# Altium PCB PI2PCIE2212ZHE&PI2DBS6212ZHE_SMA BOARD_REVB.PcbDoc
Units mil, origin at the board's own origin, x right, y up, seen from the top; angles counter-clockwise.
Board outline 7950 x 1251 mil, 4 copper layers (Top Layer, InternalPlane1, InternalPlane2, Bottom Layer); 95 components, 10 nets, 912 pads, 56 vias.
Unrouted connection lines stored in the file: 12.
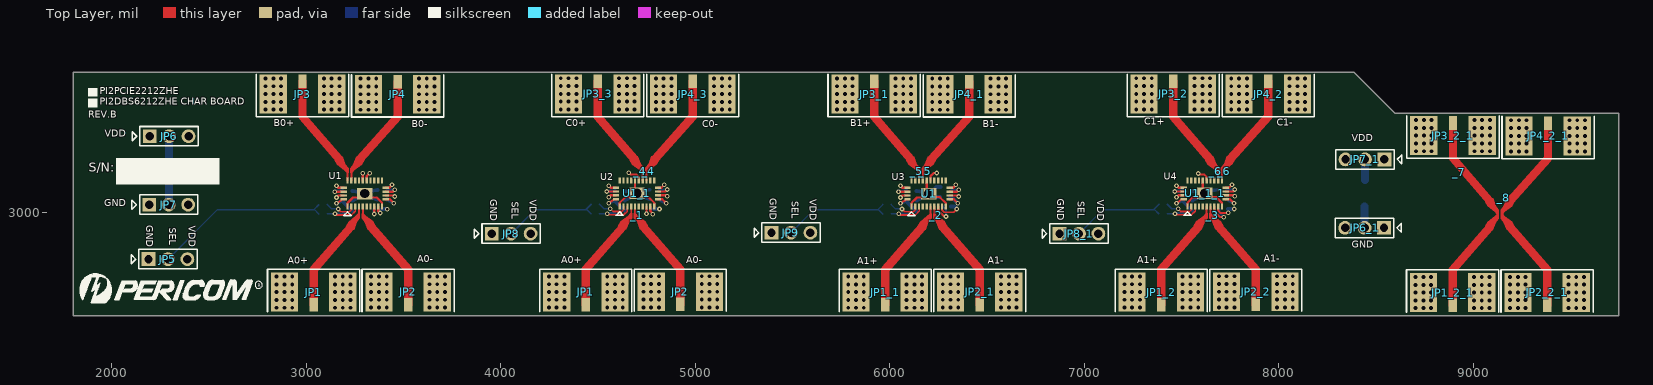
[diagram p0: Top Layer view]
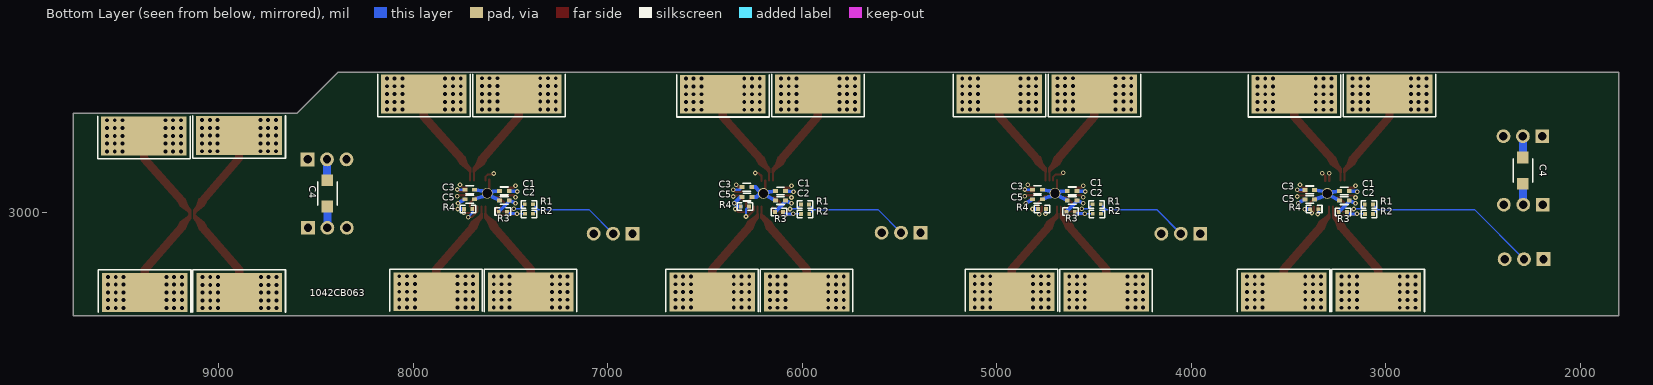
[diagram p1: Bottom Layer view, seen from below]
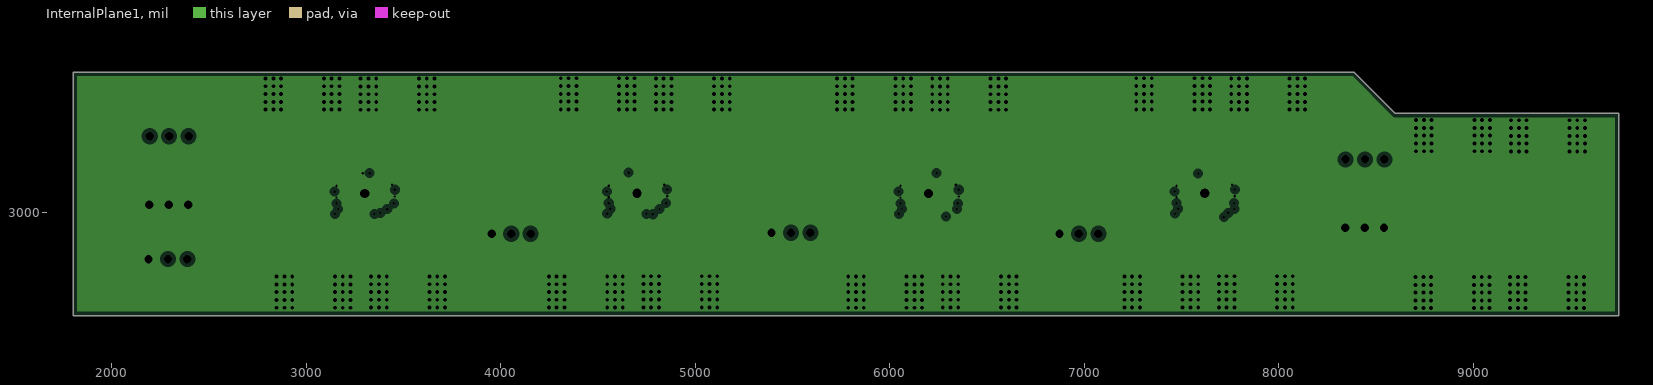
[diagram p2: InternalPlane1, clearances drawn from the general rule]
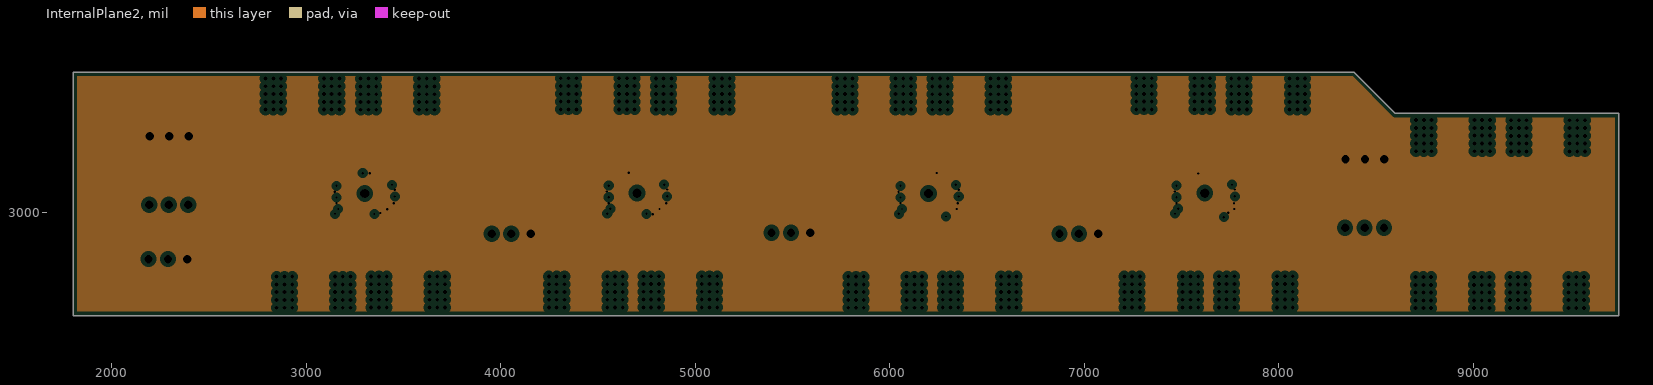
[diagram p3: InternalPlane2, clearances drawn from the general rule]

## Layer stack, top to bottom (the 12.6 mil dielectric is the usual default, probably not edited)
Top Layer: signal copper 1.4
Dielectric: core 12.6, FR-4, Dk 4.8
InternalPlane1: plane copper 1.4, net GND
Dielectric: prepreg 12.6, FR-4, Dk 4.8
InternalPlane2: plane copper 1.4, net VDD
Dielectric: core 12.6, FR-4, Dk 4.8
Bottom Layer: signal copper 1.4

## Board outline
1800,2472 9750,2472 9750,3511 8600,3511 8388,3723 1800,3723

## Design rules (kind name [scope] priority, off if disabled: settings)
Clearance [All] p1: gap=5
ComponentClearance [All] p1: gap=0 collisioncheckmode=3 verticalgap=0
HoleSize [All] p1: absolutevalues=TRUE maxlimit=500 minlimit=1 maxpercent=80.000 minpercent=20.000
PlaneClearance [All] p1: clearance=20
PlaneConnect [All] p1: planeconnectstyle=Direct reliefexpansion=20 reliefentries=4 reliefconductorwidth=10 reliefairgap=10
PolygonConnect [All] p1: connectstyle=Direct reliefconductorwidth=10 reliefentries=4 polygonreliefangle="90 Angle"
RoomDefinition "PI2DBS6212ZHE_CHAR BOAR" [InComponentClass('PI2DBS6212ZHE_CHAR BOAR')] p1: confinementstyle=ConfineIn formatcopy=TRUE lockcomponents=FALSE outline 35,220 10030,220 10030,6465 35,6465
RoutingVias [All] p1: holewidth=28 width=50 viastyle="Through Hole" minholewidth=8 minwidth=10 maxholewidth=28 maxwidth=50
SolderMaskExpansion [All] p1: expansion=4
TestPointUsage [All] p1: valid=0 allowmultiple=FALSE
Testpoint [All] p1: side=15 testpointundercomponent=TRUE minsize=40 maxsize=100 preferedsize=60 minholesize=0 maxholesize=40 preferedholesize=32 testpointgrid=1 style=1023 order=0123456789
Width [All] p1: maxlimit=150 minlimit=5 preferedwidth=10
15 further rules are at their usual default settings.

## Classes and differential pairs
component class "PI2DBS6212ZHE_CHAR BOAR": C1 C2 C3 C4 C5 JP1 JP2 JP3 JP4 JP5 JP6 JP7 R1 R2 R3 R4 U1

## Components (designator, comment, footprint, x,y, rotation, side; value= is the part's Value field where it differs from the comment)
_1 "" TRACE_650MIL_LD 4700.86,2988.73 r90 top
_2 "" TRACE_650MIL_LD 6240.23,2987.73 r90 top
_3 "" TRACE_650MIL_LD 7660.23,2988.71 r90 top
_4 "" TRACE_650MIL_LD 4718.11,3215.02 r270 top
_4 "" TRACE_650MIL_RD 4761.11,3215.02 r90 top
_5 "" TRACE_650MIL_LD 6139.37,3214.02 r270 top
_5 "" TRACE_650MIL_RD 6182.37,3214.02 r90 top
_6 "" TRACE_650MIL_LD 7677.48,3215 r270 top
_6 "" TRACE_650MIL_RD 7720.48,3215 r90 top
_7 "" TRACE_650MIL_LD 8929.1,3210.07 r270 top
_8 "" TRACE_650MIL_LD 9157.01,3078.64 r90 top
C1 "0.1u_0402" CC_0402 7532,3113 r0 bottom
C1 "0.1u_0402" CC_0402 6112,3112.02 r0 bottom
C1 "0.1u_0402" CC_0402 4612,3113.02 r0 bottom
C1 "0.1u_0402" CC_0402 3212,3112 r0 bottom
C2 "0.1u_0402" CC_0402 7532,3064 r0 bottom
C2 "0.1u_0402" CC_0402 6112,3063.02 r0 bottom
C2 "0.1u_0402" CC_0402 4612,3064.02 r0 bottom
C2 "0.1u_0402" CC_0402 3212,3063 r0 bottom
C3 "0.1u_0402" CC_0402 7710,3119 r180 bottom
C3 "0.1u_0402" CC_0402 6285,3132 r180 bottom
C3 "0.1u_0402" CC_0402 4790,3119.02 r180 bottom
C3 "0.1u_0402" CC_0402 3390,3118 r180 bottom
C4 "10u_1206" CC_1206 8442,3100 r90 bottom
C4 "10u_1206" CC_1206 2294,3217 r270 bottom
C5 "0.1u_0402" CC_0402 7710,3070 r180 bottom
C5 "0.1u_0402" CC_0402 6284,3081 r180 bottom
C5 "0.1u_0402" CC_0402 4790,3070.02 r180 bottom
C5 "0.1u_0402" CC_0402 3390,3069 r180 bottom
JP1 "RF_SMA_End" RF_SMA_End 4437,2693.02 r90 top
JP1 "RF_SMA_End" RF_SMA_End 3037,2692 r90 top
JP1_1 "RF_SMA_End" RF_SMA_End 5976.37,2692.02 r90 top (schematic designator JP1)
JP1_2 "RF_SMA_End" RF_SMA_End 7396.37,2693 r90 top (schematic designator JP1)
JP1_2_1 "RF_SMA_End" RF_SMA_End 8894.53,2689.93 r90 top (schematic designator JP1)
JP2 "RF_SMA_End" RF_SMA_End 4923,2694.02 r90 top
JP2 "RF_SMA_End" RF_SMA_End 3523,2693 r90 top
JP2_1 "RF_SMA_End" RF_SMA_End 6462.37,2693.02 r90 top (schematic designator JP2)
JP2_2 "RF_SMA_End" RF_SMA_End 7882.37,2694 r90 top (schematic designator JP2)
JP2_2_1 "RF_SMA_End" RF_SMA_End 9380.53,2690.93 r90 top (schematic designator JP2)
JP3 "RF_SMA_End" RF_SMA_End 2980,3511 r270 top
JP3_1 "RF_SMA_End" RF_SMA_End 5919.37,3511.02 r270 top (schematic designator JP3)
JP3_2 "RF_SMA_End" RF_SMA_End 7457.48,3512 r270 top (schematic designator JP3)
JP3_2_1 "RF_SMA_End" RF_SMA_End 8896.58,3297.07 r270 top (schematic designator JP3)
JP3_3 "RF_SMA_End" RF_SMA_End 4498.11,3512.02 r270 top (schematic designator JP3)
JP4 "RF_SMA_End" RF_SMA_End 3469,3510 r270 top
JP4_1 "RF_SMA_End" RF_SMA_End 6408.37,3510.02 r270 top (schematic designator JP4)
JP4_2 "RF_SMA_End" RF_SMA_End 7946.48,3511 r270 top (schematic designator JP4)
JP4_2_1 "RF_SMA_End" RF_SMA_End 9385.58,3296.07 r270 top (schematic designator JP4)
JP4_3 "RF_SMA_End" RF_SMA_End 4987.11,3511.02 r270 top (schematic designator JP4)
JP5 "3x1 Pin Header" "3x1 Pin Header" 2188,2762 r0 top
JP6 "3x1 Pin Header" "3x1 Pin Header" 2194,3394 r0 top
JP6_1 "3x1 Pin Header" "3x1 Pin Header" 8542,2923 r180 top (schematic designator JP6)
JP7 "3x1 Pin Header" "3x1 Pin Header" 2192,3042 r0 top
JP7_1 "3x1 Pin Header" "3x1 Pin Header" 8544,3275 r180 top (schematic designator JP7)
JP8 "3x1 Pin Header" "3x1 Pin Header" 3953,2893 r0 top (schematic designator JP5)
JP8_1 "3x1 Pin Header" "3x1 Pin Header" 6873,2892.98 r0 top (schematic designator JP5)
JP9 "3x1 Pin Header" "3x1 Pin Header" 5392,2898 r0 top (schematic designator JP5)
R1 "0" R_0402 3086,3043 r0 bottom
R1 "0" R_0402 5986,3043.02 r0 bottom
R1 "0" R_0402 7406,3044 r0 bottom
R1 "0" R_0402 4486,3044.02 r0 bottom
R2 "0" R_0402 3085,2994 r0 bottom
R2 "0" R_0402 5985,2994.02 r0 bottom
R2 "0" R_0402 7405,2995 r0 bottom
R2 "0" R_0402 4485,2995.02 r0 bottom
R3 "0" R_0402 3220,3005 r180 bottom
R3 "0" R_0402 6120,3005.02 r180 bottom
R3 "0" R_0402 7540,3006 r180 bottom
R3 "0" R_0402 4620,3006.02 r180 bottom
R4 "0" R_0402 3367,3019 r180 bottom
R4 "0" R_0402 4767,3020.02 r180 bottom
R4 "0" R_0402 6295,3033 r180 bottom
R4 "0" R_0402 7718,3020 r180 bottom
U1 "PI2DBS6212ZHE@TQFN28" TQFN28 6200,3099.02 r0 top
U1 "PI2DBS6212ZHE@TQFN28" TQFN28 3300,3099 r0 top
U1_1 "PI2DBS6212ZHE@TQFN28" TQFN28 4700,3100.02 r0 top (schematic designator U1)
U1_1_1 "PI2DBS6212ZHE@TQFN28" TQFN28 7620,3100 r0 top (schematic designator U1)
? "" "43 mil_Rogers" 7698.48,3222 r0 top
? "" "43 mil_Rogers" 6160.37,3221.02 r0 top
? "" "43 mil_Rogers" 4739.11,3222.02 r0 top
? "" "43 mil_Rogers" 7639.37,2983 r180 top
? "" "43 mil_Rogers" 6219.37,2982.02 r180 top
? "" "43 mil_Rogers" 4680,2983.02 r180 top
? "" TRACE_650MIL_LD 4674,3268 r270 top
? "" "43 mil_Rogers" 3221,3221 r0 top
? "" "43 mil_Rogers" 3280,2982 r180 top
? "" TRACE_650MIL_LD 7661.86,2988.72 r90 top
? "" TRACE_650MIL_LD 7493,3254 r270 top
? "" TRACE_650MIL_LD 3300.86,2987.72 r90 top
? "" TRACE_650MIL_RD 3257.86,2987.22 r270 top
? "" TRACE_650MIL_RD 3243,3214 r90 top
? "" TRACE_650MIL_LD 3200,3214 r270 top
? "" PSC_LOG 1940,2641 r0 top
? "" "43 mil_Rogers" 9137.58,3007.07 r0 top
? "" "43 mil_Rogers" 9137.53,2979.93 r180 top

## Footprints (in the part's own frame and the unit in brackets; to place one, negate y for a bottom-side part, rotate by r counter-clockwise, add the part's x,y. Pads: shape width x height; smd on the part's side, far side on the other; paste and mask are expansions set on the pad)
"3x1 Pin Header" [mm] "Pin Header 3x1 Pitch 2.54mm"
  rect 1.8x1.8 / inner round 1.8 / far side rect 1.8x1.8 hole 1.1: 1(0,0)
  round 1.8 hole 1.1: 2(2.54,0) 3(5.08,0)
  silkscreen extent -2.27,-1.27 6.35,1.27
"43 mil_Rogers" [mil]
  Top Layer region: 4.5,9.63 4.5,-13.85 14.94,-13.85 25.37,-1.93 62.99,26.75 75.28,47.48 74.23,68.36 35.23,68.36 20.51,30.23
  Top Layer region: -25.14,-2.29 -62.76,26.39 -75.05,47.12 -74,68 -35,68 -20.27,29.87 -4.5,9.57 -4.5,-14.21 -14.82,-14.21
CC_0402 [mil]
  rect 25x20 smd: 1(-25,0) 2(25,0)
  silkscreen extent -20,-20 20,20
CC_1206 [mil]
  rect 60x60 smd: 1(-67.5,0) 2(67.5,0)
  silkscreen extent -60,-50 60,50
PSC_LOG [mil]
  silkscreen extent -107,-103 833,45
R_0402 [mm]
  rect 0.5x0.5 smd: 1(-0.532,-0.001) 2(0.54,-0.001)
  silkscreen extent -1.02,-0.49 1.02,0.49
RF_SMA_End [mil] "PSF-S01B-2_FR4"
  rect 70x43 smd: 1(-165,0)
  rect 200x140 smd: 2(-100,-150) 3(-100,150)
  round 25 / inner round 35 / far side round 25 hole 20: 20(-180.02,190) 20(-180,-190) 20(-180,-150) 20(-180,-110) 20(-180,-110) 20(-180,110) 20(-180,150) 20(-140,-190) 20(-140,-150) 20(-140,110) 20(-140,150) 20(-140,190) 20(-140,-110) 20(-100,150) 20(-100,190) 20(-100,-110) 20(-100,110) 20(-100,-190) 20(-100,-150) 20(-60,190) 20(-60,110) 20(-60,150) 20(-60,-150) 20(-60,-110) 20(-60,-190) 20(-20,110) 20(-20,150) 20(-20,190) 20(-20,-110) 20(-20,-190) 20(-20,-150)
  rect 200x440 smd far side: 34(-100,0)
  silkscreen extent -201,-237 17,237
TQFN28 [mm] "TQFN28, 3.4x5.6mm, M10x4, Pitch 0.5mm"
  rect 0.3x0.8 smd: 1(-2.25,-1.7) 2(-1.75,-1.7) 3(-1.25,-1.7) 4(-0.75,-1.7) 5(-0.25,-1.7) 6(0.25,-1.7) 7(0.75,-1.7) 8(1.25,-1.7) 9(1.75,-1.7) 10(2.25,-1.7) 15(2.25,1.7) 16(1.75,1.7) 17(1.25,1.7) 18(0.75,1.7) 19(0.25,1.7) 20(-0.25,1.7) 21(-0.75,1.7) 22(-1.25,1.7) 23(-1.75,1.7) 24(-2.25,1.7)
  rect 0.8x0.3 smd: 11(2.75,-0.75) 12(2.75,-0.25) 13(2.75,0.25) 14(2.75,0.75) 25(-2.75,0.75) 26(-2.75,0.25) 27(-2.75,-0.25) 28(-2.75,-0.75)
  rect 2x1.5 smd: 29(0,0)
  round 1.4 hole 1.2: 29(0,0.025)
  silkscreen extent -2.74,-2.87 -1.78,-2.39
TRACE_650MIL_LD [mil]
TRACE_650MIL_RD [mil]

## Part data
C1 C1 C1 C1 C2 C2 C2 C2 C3 C3 C3 C3 C5 C5 C5 C5: library part C_0.1u_0402
C4 C4: library part C_10u_1206
R1 R1 R1 R1 R2 R2 R2 R2 R3 R3 R3 R3 R4 R4 R4 R4: library part "CHIP RES0402"

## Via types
v1: diameter 24, hole 12, Top Layer to Bottom Layer, tented both sides, 56 vias

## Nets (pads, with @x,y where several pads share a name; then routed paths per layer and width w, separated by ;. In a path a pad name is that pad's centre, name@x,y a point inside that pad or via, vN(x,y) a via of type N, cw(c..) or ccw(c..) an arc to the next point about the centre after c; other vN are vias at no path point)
A0+: JP1.1@3037,2527 U1.4@3270.47,3032.07 | length 516.6
  Top Layer w10: 3270.47,2986 U1.4@3270.47,3032.07
  Top Layer w43: JP1.1@3037,2527 3037,2709 3226.78,2926.32
A0-: JP2.1@3523,2528 U1.5@3290.16,3032.07 | length 517.2
  Top Layer w10: 3290.16,2985 U1.5@3290.16,3032.07
  Top Layer w43: 3333.15,2927.13 3523,2709 JP2.1@3523,2528
B0+: JP3.1 U1.24@3211.42,3165.93 | length 516.8
  Top Layer w10: U1.24@3211.42,3165.93 3211.42,3213.59
  Top Layer w43: JP3.1 2980,3494 3167.58,3276.64
B0-: JP4.1 U1.23@3231.1,3165.93 | length 520.8
  Top Layer w10: U1.23@3231.1,3165.93 3231.1,3213.29
  Top Layer w43: 3274.06,3275.95 3469,3494 JP4.1
GND: C1.2 C2.2 C3.2 C4.1@8442,3032.5 C4.2@2294,3149.5 C5.2 JP1.2 JP1.3 JP1.20 JP1.34 JP1_1.2 JP1_1.3 JP1_1.20 JP1_1.34 JP1_2.2 JP1_2.3 JP1_2.20 JP1_2.34 JP1_2_1.2 JP1_2_1.3 JP1_2_1.20 JP1_2_1.34 JP2.2 JP2.3 JP2.20 JP2.34 JP2_1.2 JP2_1.3 JP2_1.20 JP2_1.34 JP2_2.2 JP2_2.3 JP2_2.20 JP2_2.34 JP2_2_1.2 JP2_2_1.3 JP2_2_1.20 JP2_2_1.34 JP3.2 JP3.3 JP3.20 JP3.34 JP3_1.2 JP3_1.3 JP3_1.20 JP3_1.34 JP3_2.2 JP3_2.3 JP3_2.20 JP3_2.34 JP3_2_1.2 JP3_2_1.3 JP3_2_1.20 JP3_2_1.34 JP3_3.2 JP3_3.3 JP3_3.20 JP3_3.34 JP4.2 JP4.3 JP4.20 JP4.34 JP4_1.2 JP4_1.3 JP4_1.20 JP4_1.34 JP4_2.2 JP4_2.3 JP4_2.20 JP4_2.34 JP4_2_1.2 JP4_2_1.3 JP4_2_1.20 JP4_2_1.34 JP4_3.2 JP4_3.3 JP4_3.20 JP4_3.34 JP5.1 JP6_1.1 JP6_1.2 JP6_1.3 JP7.1 JP7.2 JP7.3 JP8.1 JP8_1.1 JP9.1 U1.1 U1.10 U1.12 U1.14 U1.20 U1.25 U1.27 U1.29 U1_1.1 U1_1.10 U1_1.12 U1_1.14 U1_1.20 U1_1.25 U1_1.27 U1_1.29 U1_1_1.1 U1_1_1.10 U1_1_1.12 U1_1_1.14 U1_1_1.20 U1_1_1.25 U1_1_1.27 U1_1_1.29 | length 2426.7
  Top Layer w11: U1.29@3328,3079 3361,3079 3388.58,3051.42 U1.10@3388.58,3032.07 ; U1_1.1 4611.42,3052.42 4640,3081 U1_1.29@4674,3081 ; U1_1.29@4732,3086 4754,3086 4788.58,3051.42 U1_1.10 ; U1.1@6111.42,3032.09 6111.42,3050.42 6140,3079 U1.29@6170,3079 ; U1.29@6230,3081 6258,3081 6288.58,3050.42 U1.10@6288.58,3032.09 ; U1_1_1.1 7531.42,3052.42 7559,3080 U1_1_1.29@7587,3080
  Top Layer w12: v1(3155,3079) 3165.16,3089.16 U1.27@3191.73,3089.16 ; v1(3155,3139) 3165.47,3128.53 U1.25@3191.73,3128.53 ; U1.1@3211.42,3032.07 3211.42,3051.42 3239,3079 U1.29@3266,3079 ; U1.20@3290.16,3165.93 v1@3290.16,3204 ; U1.12@3408.27,3089.16 3449.84,3089.16 v1(3455,3084) ; U1.14@3408.27,3128.53 3424.53,3128.53 v1(3440,3144) ; v1(4555,3080.02) 4565.16,3090.17 U1_1.27 ; v1(4555,3140.02) 4565.47,3129.54 U1_1.25 ; U1_1.29@4690.16,3123.84 U1_1.20 ; U1_1.12 4849.84,3090.17 v1(4855,3085.02) ; U1_1.14 4824.53,3129.54 v1(4840,3145.02) ; v1(6055,3079.02) 6065.16,3089.17 U1.27@6091.73,3089.17 ; v1(6055,3139.02) 6065.47,3128.54 U1.25@6091.73,3128.54 ; U1.29@6190,3112 U1.20@6190,3165.94 ; U1.12@6308.27,3089.17 6349.84,3089.17 v1(6355,3084.02) ; U1.14@6308.27,3128.54 6324.53,3128.54 v1(6340,3144.02) ; v1(7475,3080) 7485.16,3090.16 U1_1_1.27 ; v1(7475,3140) 7485.47,3129.53 U1_1_1.25 ; U1_1_1.29@7610,3127 U1_1_1.20@7610,3170.1 ; U1_1_1.29@7651,3080 7680,3080 7708.58,3051.42 U1_1_1.10 ; U1_1_1.12 7769.84,3090.16 v1(7775,3085) ; U1_1_1.14 7744.53,3129.53 v1(7760,3145)
  Bottom Layer w20: C2.2@3237,3063 3274,3083 ; C1.2@3237,3112 3271,3108 ; 3323,3084 C5.2@3365,3069 ; U1.29@3325,3111 C3.2@3365,3118 ; C2.2@4637,3064 4674,3084 ; C1.2@4637,3113 4671,3109 ; 4723,3085 C5.2@4765,3070 ; U1_1.29@4725,3112 C3.2@4765,3119 ; C2.2@6137,3063 6174,3083 ; C1.2@6137,3112 6171,3108 ; U1.29@6222,3113 6241,3132 C3.2@6260,3132 ; U1.29@6225,3092 6236,3081 C5.2@6259,3081 ; C2.2@7557,3064 7594,3084 ; C1.2@7557,3113 7591,3109 ; 7643,3085 C5.2@7685,3070 ; U1_1_1.29@7645,3112 C3.2@7685,3119
  Bottom Layer w40: JP7.2@2294,3044 C4.2@2294,3149.5 ; JP6_1.2@8442,2923.5 C4.1@8442,3033
  other v1: 3290,3204
NetR1_2: R1.2 U1.2 U1_1.2 U1_1_1.2 | length 639.6
  Top Layer w8: v1(3163,3020) 3177,3006 3222,3006 3231.1,3015.1 U1.2@3231.1,3032.07 ; v1(4563,3021.02) 4577,3007.02 4622,3007.02 4631.1,3016.12 U1_1.2 ; v1(6063,3020.02) 6077,3006.02 6122,3006.02 6131.1,3015.12 U1.2@6131.1,3032.09 ; v1(7483,3021) 7497,3007 7542,3007 7551.1,3016.1 U1_1_1.2
  Bottom Layer w8: R1.2@3107.27,3043.03 3130.3,3020 v1(3163,3020) ; R1.2@4506.97,3044.03 4530,3021 v1@4562.7,3021 ; R1.2@6006.97,3043.03 6030,3020 v1@6062.7,3020 ; R1.2@7427.27,3044.03 7450.3,3021 v1(7483,3021)
NetR2_2: R2.2@3106.27,2994.03 R3.2@3198.73,3004.97 U1.3@3250.79,3032.07 | length 234
  Top Layer w8: v1(3147,2995) 3153,2989 3232,2989 3250.79,3007.79 U1.3@3250.79,3032.07
  Bottom Layer w8: R2.2@3107.24,2995 v1(3147,2995)
  Bottom Layer w15: v1(3147,2995) 3188.76,2995 R3.2@3198.73,3004.97
NetR4_2: R4.2 U1.8 U1_1.8 U1_1_1.8 | length 393.2
  Top Layer w11: v1(3349.21,2993.79) U1.8@3349.21,3032.07 ; v1(4749.21,2994.8) U1_1.8 ; U1.8@6249.21,3032.09 6249.21,3011.79 6280,2981 v1(6289,2981) ; U1_1_1.8 7669.21,3007.79 7699,2978 v1(7718,2978)
  Bottom Layer w11: R4.2@3345.73,3018.97 3345.73,2997.27 v1(3349.21,2993.79) ; v1(4749.21,2994.8) R4.2@4749.21,3016.5 ; R4.2@6273.73,3032.97 6289,3017.7 v1(6289,2981) ; R4.2@7696.73,3019.97 7696.73,2999.27 v1(7718,2978)
SEL: JP5.2 JP8.2 JP8_1.2 JP9.2 R1.1 R2.1 R2.2@4506.27,2995.05 R2.2@6006.27,2994.05 R2.2@7426.27,2995.03 R3.2@4598.73,3005.98 R3.2@6098.73,3004.98 R3.2@7518.73,3005.97 U1.3@6150.79,3032.09 U1_1.3 U1_1_1.3 | length 3173.9
  Top Layer w8: v1(4547,2996.02) 4553,2990.02 4632,2990.02 4650.79,3008.8 U1_1.3 ; v1(6047,2995.02) 6053,2989.02 6132,2989.02 6150.79,3007.8 U1.3@6150.79,3032.09 ; v1(7467,2996) 7473,2990 7552,2990 7570.79,3008.79 U1_1_1.3
  Bottom Layer w8: JP5.2 2543,3017 3041.08,3017 R2.1@3064.05,2994.03 ; 3039,3017 R1.1@3064,3042 ; JP8.2 4176,3016 4443.1,3016 R2.1@4464.05,2995.05 ; 4437,3016 R1.1@4465.05,3044.05 ; R2.2@4507.24,2996.02 v1(4547,2996.02) ; JP9.2 5611,3017 5941.1,3017 R2.1@5964.05,2994.05 ; 5939,3017 R1.1@5965.05,3043.05 ; R2.2@6007.24,2995.02 v1(6047,2995.02) ; JP8_1.2 7097.02,3017 7362.08,3017 R2.1@7384.05,2995.03 ; 7358.02,3017 R1.1@7385.05,3044.03 ; R2.2@7427.24,2996 v1(7467,2996)
  Bottom Layer w15: v1(4547,2996.02) 4588.76,2996.02 ; v1(6047,2995.02) 6088.76,2995.02 ; v1(7467,2996) 7508.76,2996
VDD: C1.1 C2.1 C3.1 C4.1@2294,3284.5 C4.2@8442,3167.5 C5.1 JP5.3 JP6.1 JP6.2 JP6.3 JP7_1.1 JP7_1.2 JP7_1.3 JP8.3 JP8_1.3 JP9.3 R3.1 R4.1 U1.9 U1.11 U1.13 U1.19 U1.26 U1.28 U1_1.9 U1_1.11 U1_1.13 U1_1.19 U1_1.26 U1_1.28 U1_1_1.9 U1_1_1.11 U1_1_1.13 U1_1_1.19 U1_1_1.26 U1_1_1.28 | length 2583.6
  Top Layer w10: v1(4657,3207) 4667,3197 4698,3197 4709.84,3185.16 U1_1.19 ; U1.9@6268.9,3032.09 6268.9,3014.1 6280,3003 6328.06,3003 v1(6345.03,3019.97) ; v1(7586,3202) 7591.02,3196.98 7618,3196.98 7629.84,3185.14 U1_1_1.19 ; U1_1_1.9 7688.9,3011.1 7700,3000 v1(7741,3000)
  Top Layer w12: v1@3145,3108.84 U1.26@3191.73,3108.84 ; v1(3155,3049) 3185.47,3069.47 U1.28@3191.73,3069.47 ; U1.19@3309.84,3165.93 3309.84,3188.84 v1(3325,3204) ; U1.9@3368.9,3032.07 3368.9,3010.1 v1(3380,2999) ; U1.11@3408.27,3069.47 3429.53,3069.47 v1(3450,3049) ; U1.13@3408.27,3108.84 3444.84,3108.84 v1(3455,3119) ; v1(4545,3109.86) U1_1.26 ; v1(4555,3050.02) 4585.47,3070.49 U1_1.28 ; U1_1.9 4768.9,3011.12 v1(4782,2993) ; U1_1.11 4829.53,3070.49 v1(4850,3050.02) ; U1_1.13 4844.84,3109.86 v1(4855,3120.02) ; v1(6045,3108.86) U1.26@6091.73,3108.86 ; v1(6055,3049.02) 6085.47,3069.49 U1.28@6091.73,3069.49 ; U1.19@6209.84,3165.94 6209.84,3188.86 6225.98,3205 v1(6241,3205) ; U1.11@6308.27,3069.49 6329.53,3069.49 v1(6350,3049.02) ; U1.13@6308.27,3108.86 6344.84,3108.86 v1(6355,3119.02) ; v1(7465,3109.84) U1_1_1.26 ; v1(7475,3050) 7505.47,3070.47 U1_1_1.28 ; U1_1_1.11 7749.53,3070.47 v1(7770,3050) ; U1_1_1.13 7764.84,3109.84 v1(7775,3120)
  Bottom Layer w14: C3.1@6310,3132 6322.98,3119.02 v1(6355,3119.02)
  Bottom Layer w15: C3.1@3415,3118 v1(3455,3119) ; C3.1@4815,3119.02 v1(4855,3120.02) ; C3.1@7735,3119 v1(7775,3120)
  Bottom Layer w20: v1(3145,3109) C1.1@3187,3112 ; v1(3155,3049) 3185.5,3062.34 C2.1@3187,3063 ; C2.1@3187,3058.92 R3.1@3240.95,3004.97 ; R4.1@3387.95,3018.97 v1(3415.97,3018.97) ; C5.1@3415,3069 v1(3450,3049) ; v1(4545,3109.86) C1.1@4587,3112.86 ; v1(4555,3050.02) C2.1@4587,3064.02 ; C2.1@4587,3059.94 R3.1@4640.95,3005.98 ; R4.1@4787.95,3019.98 v1(4815.97,3019.98) ; C5.1@4815,3070.02 v1(4850,3050.02) ; v1(6045,3108.86) C1.1@6087,3111.86 ; v1(6055,3049.02) C2.1@6087,3063.02 ; C2.1@6087,3058.94 R3.1@6140.95,3004.98 ; C5.1@6309,3081 6318.02,3081 v1(6350,3049.02) ; R4.1@6313.92,3033 6332,3033 v1(6345.03,3019.97) ; v1(7465,3109.84) C1.1@7507,3112.84 ; v1(7475,3050) C2.1@7507,3064 ; C2.1@7507,3059.92 R3.1@7560.95,3005.97 ; C5.1@7735,3070 v1(7770,3050) ; R4.1@7738.95,3019.97 v1(7772,3020)
  Bottom Layer w40: C4.1@2294,3284.5 JP6.2 ; C4.2@8444,3169.5 JP7_1.2
pads on no net: JP1.1@4437,2528.02 JP1_1.1 JP1_2.1 JP1_2_1.1 JP2.1@4923,2529.02 JP2_1.1 JP2_2.1 JP2_2_1.1 JP3_1.1 JP3_2.1 JP3_2_1.1 JP3_3.1 JP4_1.1 JP4_2.1 JP4_2_1.1 JP4_3.1 U1.4@6170.47,3032.09 U1.5@6190.16,3032.09 U1.6 U1.7 U1.15 U1.16 U1.17 U1.18 U1.21 U1.22 U1.23@6131.1,3165.94 U1.24@6111.42,3165.94 U1_1.4 U1_1.5 U1_1.6 U1_1.7 U1_1.15 U1_1.16 U1_1.17 U1_1.18 U1_1.21 U1_1.22 U1_1.23 U1_1.24 U1_1_1.4 U1_1_1.5 U1_1_1.6 U1_1_1.7 U1_1_1.15 U1_1_1.16 U1_1_1.17 U1_1_1.18 U1_1_1.21 U1_1_1.22 U1_1_1.23 U1_1_1.24
copper on no net: | length 8134.3
  Top Layer w10: 4670.47,2978.42 4670.47,3033.09 ; 4690.16,2981.02 4690.16,3033.09 ; 4729.53,3166.94 4729.53,3214.61 ; 4749.21,3166.94 4749.21,3214.3 ; 6150.79,3165.95 6150.79,3213.61 ; 6170.47,3165.95 6170.47,3213.3 ; 6209.84,2977.42 6209.84,3032.09 ; 6229.53,2980.02 6229.53,3032.09 ; 7629.84,2978.4 7629.84,3033.07 ; 7649.53,2981 7649.53,3033.07 ; 7688.9,3166.93 7688.9,3214.59 ; 7708.58,3166.93 7708.58,3214.28
  Top Layer w43: 4437,2528.02 4437,2710.02 4625.78,2926.2 ; 4498.11,3677.02 4498.11,3495.02 4686.22,3277.05 ; 4733.59,2927.64 4923,2710.02 4923,2529.02 ; 4793.11,3278.02 4987.11,3495.02 4987.11,3676.02 ; 5919.37,3676.02 5919.37,3494.02 6107.3,3276.26 ; 5976.37,2527.02 5976.37,2709.02 6164.92,2924.94 ; 6214.37,3277.02 6408.37,3494.02 6408.37,3675.02 ; 6272.37,2927.32 6462.37,2709.02 6462.37,2528.02 ; 7396.37,2528 7396.37,2710 7586.35,2927.56 ; 7457.48,3677 7457.48,3495 7645.35,3277.31 ; 7692.36,2928.31 7882.37,2710 7882.37,2529 ; 7751.82,3277.26 7946.48,3495 7946.48,3676 ; 8894.53,2524.93 8894.53,2706.93 9084.51,2924.49 ; 8896.58,3462.07 8896.58,3280.07 9084.46,3062.38 ; 9190.52,2925.24 9380.53,2706.93 9380.53,2525.93 ; 9190.93,3062.34 9385.58,3280.07 9385.58,3461.07

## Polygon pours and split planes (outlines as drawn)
no net on Top Solder "bottom Layer-No Net" (solid): 8675,3277 9606,3277 9606,2825.61 9606,2711 8677,2711 8675,2711 8675,3277
no net on Top Solder "bottom Layer-No Net" (solid): 7134,3491 8195,3491 8196,3492 8196,2714 7135,2714 7134,2715 7134,3491
no net on Top Solder "bottom Layer-No Net" (solid): 5677,3489.41 6738,3489.41 6739,3490.41 6739,2712.41 5678,2712.41 5677,2713.41 5677,3489.41
no net on Top Solder "bottom Layer-No Net" (solid): 4199,3491 5260,3491 5261,3492 5261,2714 4200,2714 4199,2715 4199,3491
no net on Top Solder "bottom Layer-No Net" (solid): 2738,3491 3799,3491 3800,3492 3800,2714 2739,2714 2738,2715 2738,3491
GND on InternalPlane1 (split plane): 8585.58,3496.58 8592.2,3492.16 8600,3490.61 9729.61,3490.61 9729.61,2492.39 1820.39,2492.39 1820.39,3702.61 8379.55,3702.61
VDD on InternalPlane2 (split plane): 8585.58,3496.58 8592.2,3492.16 8600,3490.61 9729.61,3490.61 9729.61,2492.39 1820.39,2492.39 1820.39,3702.61 8379.55,3702.61

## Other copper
Top Layer:
  text "TOP LAYER" at 10796,2656 h80
  text "1" at 11184,2526 h80
Bottom Layer:
  text "BOTTOM LAYER" at 10796,2656 h80
  text "4" at 11184,2526 h80
InternalPlane1 (plane layer: these items are gaps in the copper):
  text "GND PLANE LAYER" at 10796,2656 h80
  text "2" at 11184,2526 h80
InternalPlane2 (plane layer: these items are gaps in the copper):
  text "POWER PLANE LAYER" at 10796,2656 h80
  text "3" at 11184,2526 h80

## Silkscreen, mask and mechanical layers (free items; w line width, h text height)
Top Overlay:
  rectangle: 2020,3147 2552,3282
  rectangle: 1877,3597.36 1926,3643
  rectangle: 1877,3541.36 1926,3587
  text "PI2PCIE2212ZHE" at 1936,3598 h60
  text "PI2DBS6212ZHE CHAR BOARD" at 1936,3544 h60
  text "REV.B" at 1877,3476 h60
  text "C1+" at 7310,3439 h60
  text "C1-" at 7989,3435 h60
  text "B0+" at 2833,3432 h60
  text "C0+" at 4333,3432 h60
  text "B1+" at 5796,3432 h60
  text "B0-" at 3542,3428 h60
  text "C0-" at 5037,3428 h60
  text "B1-" at 6479,3428 h60
  text "VDD" at 1963,3379 h60
  text "VDD" at 8375,3356 h60
  text "S/N:" at 1881,3197 h80
  text "U4" at 7409,3157 h60
  text "U3" at 6011,3155 h60
  text "U2" at 4510,3154 h60
  text "GND" at 5369,3075 h60 r270
  text "GND" at 6849,3072 h60 r270
  text "GND" at 3932,3071 h60 r270
  text "VDD" at 5575,3071 h60 r270
  text "VDD" at 4137,3068 h60 r270
  text "VDD" at 7055,3067 h60 r270
  text "SEL" at 5483,3060 h60 r270
  text "SEL" at 6954,3059 h60 r270
  text "SEL" at 4042,3057 h60 r270
  text "GND" at 1961,3021 h60
  text "GND" at 2164,2937 h60 r270
  text "VDD" at 2381,2933 h60 r270
  text "SEL" at 2282,2924 h60 r270
  text "GND" at 8376,2807 h60
  text "A1-" at 7923,2736 h60
  text "A0-" at 3571,2733 h60
  text "A0-" at 4954,2729 h60
  text "A1+" at 7274,2729 h60
  text "A0+" at 4310,2727 h60
  text "A0+" at 2905,2726 h60
  text "A1-" at 6504,2726 h60
  text "A1+" at 5833,2724 h60
  text "TOP SILKSCREEN LAYER" at 10796,2656 h80
  text "5" at 11184,2526 h80
Bottom Overlay:
  text "BOTTOM SILKSCREEN LAYER" at 10796,2656 h80
  text "1042CB063" at 8534,2558 h60
  text "6" at 11184,2526 h80
Top Paste:
  text "TOP PASTE LAYER" at 10796,2656 h80
  text "TOP PASTE LAYER" at 10796,2656 h80
  text "TP" at 11164,2526 h80
Bottom Paste:
  text "BOTTOM PASTE LAYER" at 10796,2656 h80
  text "BOTTOM PASTE LAYER" at 10796,2656 h80
  text "BP" at 11164,2526 h80
Top Solder:
  pour cut-out: 7970,3482 8093,3482 8093,3426 7970,3426
  pour cut-out: 7302,3481 7415,3481 7415,3428 7302,3428
  pour cut-out: 7262,2776 7373,2776 7373,2723 7262,2723
  pour cut-out: 7909,2780 7909,2730 8013,2730 8013,2780
  pour cut-out: 6457.5,3475 6580.5,3475 6580.5,3419 6457.5,3419
  pour cut-out: 5782,3477.41 5895,3477.41 5895,3424.41 5782,3424.41
  pour cut-out: 5828,2769.5 5939,2769.5 5939,2716.5 5828,2716.5
  pour cut-out: 6497,2770 6497,2720 6601,2720 6601,2770
  pour cut-out: 4949,2775 4949,2725 5053,2725 5053,2775
  pour cut-out: 4302,2771 4413,2771 4413,2718 4302,2718
  pour cut-out: 3560,2775 3560,2726 3676,2726 3676,2775
  pour cut-out: 2888,2777 2888,2720 3005,2720 3005,2777
  pour cut-out: 4318,3480 4431,3480 4431,3427 4318,3427
  pour cut-out: 5019.5,3477 5142.5,3477 5142.5,3421 5019.5,3421
  pour cut-out: 3516,3475 3639,3475 3639,3419 3516,3419
  pour cut-out: 2819.5,3476 2932.5,3476 2932.5,3423 2819.5,3423
  pour cut-out: 7400,3206 7844,3206 7844,2986 7400,2986
  pour cut-out: 4500,3211 4500,2994 4900,2994 4900,3210 4700,3210
  pour cut-out: 3100,2996 3500,2996 3500,3209 3100,3209
  pour cut-out: 6000,3208 6000,2996 6400,2996 6400,3209 6200,3208
  lines w50: 2980,3674 2980,3492 3006,3466 ; 3037,2540 3037,2710 3067,2740 ; 3443,3471 3468,3496 3468,3679 ; 3495,2735 3522,2708 3522,2547 ; 4436,2541 4436,2704 4472,2740 ; 4498,3477 4498,3681 ; 4890,2744 4922,2712 4922,2544 ; 4968,3477 4987,3496 4987,3685 ; 5918,3684 5918,3499 5939,3478 ; 5976,2538 5976,2701 6013,2738 ; 6383,3473 6408,3498 6408,3676 ; 6439,2730 6463,2706 6463,2538 ; 7397,2535 7397,2708 7424,2735 ; 7457,3671 7457,3495 7485,3467 ; 7882,2519 7882,2723 ; 7927,3479 7948,3500 7948,3684 ; 8895.16,2531.93 8895.16,2704.93 8922.16,2731.93 ; 8896.1,3456.07 8896.1,3280.07 8924.1,3252.07 ; 9366.1,3264.07 9387.1,3285.07 9387.1,3469.07 ; 9380.16,2515.93 9380.16,2719.93
  text "TOP SOLDER LAYER" at 10796,2656 h80
  text "7" at 11184,2526 h80
Bottom Solder:
  text "BOTTOM SOLDER LAYER" at 10796,2656 h80
  text "8" at 11184,2526 h80
Drill Guide:
  text "DRILL GUIDE LAYER" at 10796,2656 h80
  text "10" at 11164,2526 h80
Mechanical 1:
  lines w8: 1800,2472 1800,3723 8388,3723 8600,3511 9750,3511 9750,2472 8595,2472 1800,2472
  lines w10: 10504,2616 10504,3006 ; 10904,2486 10904,2616 ; 10904,2746 10904,2876 ; 11434,2746 11434,2876
  lines w12: 9984,2616 12508,2616 ; 9984,2746 12508,2746 ; 9984,2876 12508,2876 ; 9984,3006 12508,3006 ; 9984,3066 10549,3066 ; 9984,3116 10495,3116 ; 9984,3166 10576,3166 ; 11524,3066 12508,3066 ; 11524,3166 12508,3166 ; 11614,3116 12508,3115
  lines w15: 9984,2486 12508,2486 12508,3236 9984,3236 9984,2486
  text "Pericom" at 10738,3067 h180
  text "PCB NAME" at 10024,2916 h60
  text "PI2PCIE2212ZHE&PI2DBS6212ZHE CHAR BOARD" at 10534,2916 h80
  text "REV.B" at 12260,2916 h80
  text "DATE" at 10114,2786 h60
  text "8/10/2010" at 10524,2786 h80
  text "Drawn by" at 10934,2786 h60
  text "Haojie Ci" at 11484,2786 h80
  text "TITLE" at 10094,2656 h60
  text "SHEET NUMBER" at 10104,2526 h60
  text "OF       10" at 11404,2526 h80
Drill Drawing:
  lines w10: 10134,4216 10134,4706 ; 10214,3586 10424,3586 ; 10214,3926 10424,3926 ; 10294,3646 10314,3586 ; 10294,3866 10314,3926 ; 10314,3696 10314,3586 ; 10314,3816 10314,3926 ; 10334,3646 10314,3586 ; 10334,3866 10314,3926 ; 10524,4216 10524,4706 ; 11434,4216 11434,4706 ; 12574,4216 12574,4706 ; 10514,3586 10514,3636 11554,3636 11554,3586 10514,3586 ; 10514,3677 10514,3727 11554,3727 11554,3677 10514,3677 ; 10514,3777 10514,3827 11554,3827 11554,3777 10514,3777 ; 10514,3876 11554,3876 11554,3926 10514,3926 10514,3876
  lines w12: 9654,4346 13174,4346 ; 9654,4476 13174,4476
  lines w15: 9654,4216 9654,4706 13174,4706 13174,4216 9654,4216
  text "IMPEDANCE CHART" at 9654,4736 h100
  text "TRACE" at 10204,4596 h60
  text "SINGLE-ENDED" at 10554,4596 h60
  text "DIFFERENTIAL-ENDED" at 11494,4596 h60
  text "LAYER(S)" at 9694,4556 h60
  text "TOLERANCE" at 12614,4556 h60
  text "TYPE" at 10204,4516 h60
  text "IMPEDANCE REQ'D" at 10554,4516 h60
  text "IMPEDANCE REQ'D" at 11494,4516 h60
  text "+/- 10%" at 12754,4396 h80
  text "--" at 10298,4392 h80
  text "--" at 10925,4392 h80
  text "--" at 11945,4392 h80
  text "1" at 9884,4386 h80
  text "50 ohm" at 10838,4262 h80
  text "--" at 11943,4258 h80
  text "1" at 9884,4256 h80
  text "+/- 10%" at 12754,4256 h80
  text "43 mil" at 10243,4255 h80
  text "LAYER1 SIGNAL" at 11595,3877 h80
  text "LAYER2 GROUND PLANE" at 11595,3777 h80
  text "THICKNESS is 1.6mm" at 9515,3737 h80
  text "LAYER3 PWR PLANE" at 11595,3677 h80
  text "LAYER4 SIGNAL" at 11595,3587 h80
  text "DRILL DRAWING LAYER" at 10796,2656 h80
  text "9" at 11184,2526 h80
